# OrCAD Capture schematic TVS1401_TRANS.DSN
size C; title: TVS1401 14-V Bidirectional Flat-Clamp Surge Protection Device; rev: 1.0; note: Datasheet:SLVSEQ2    EVM: NA; note: Synchronous Step Down Converter
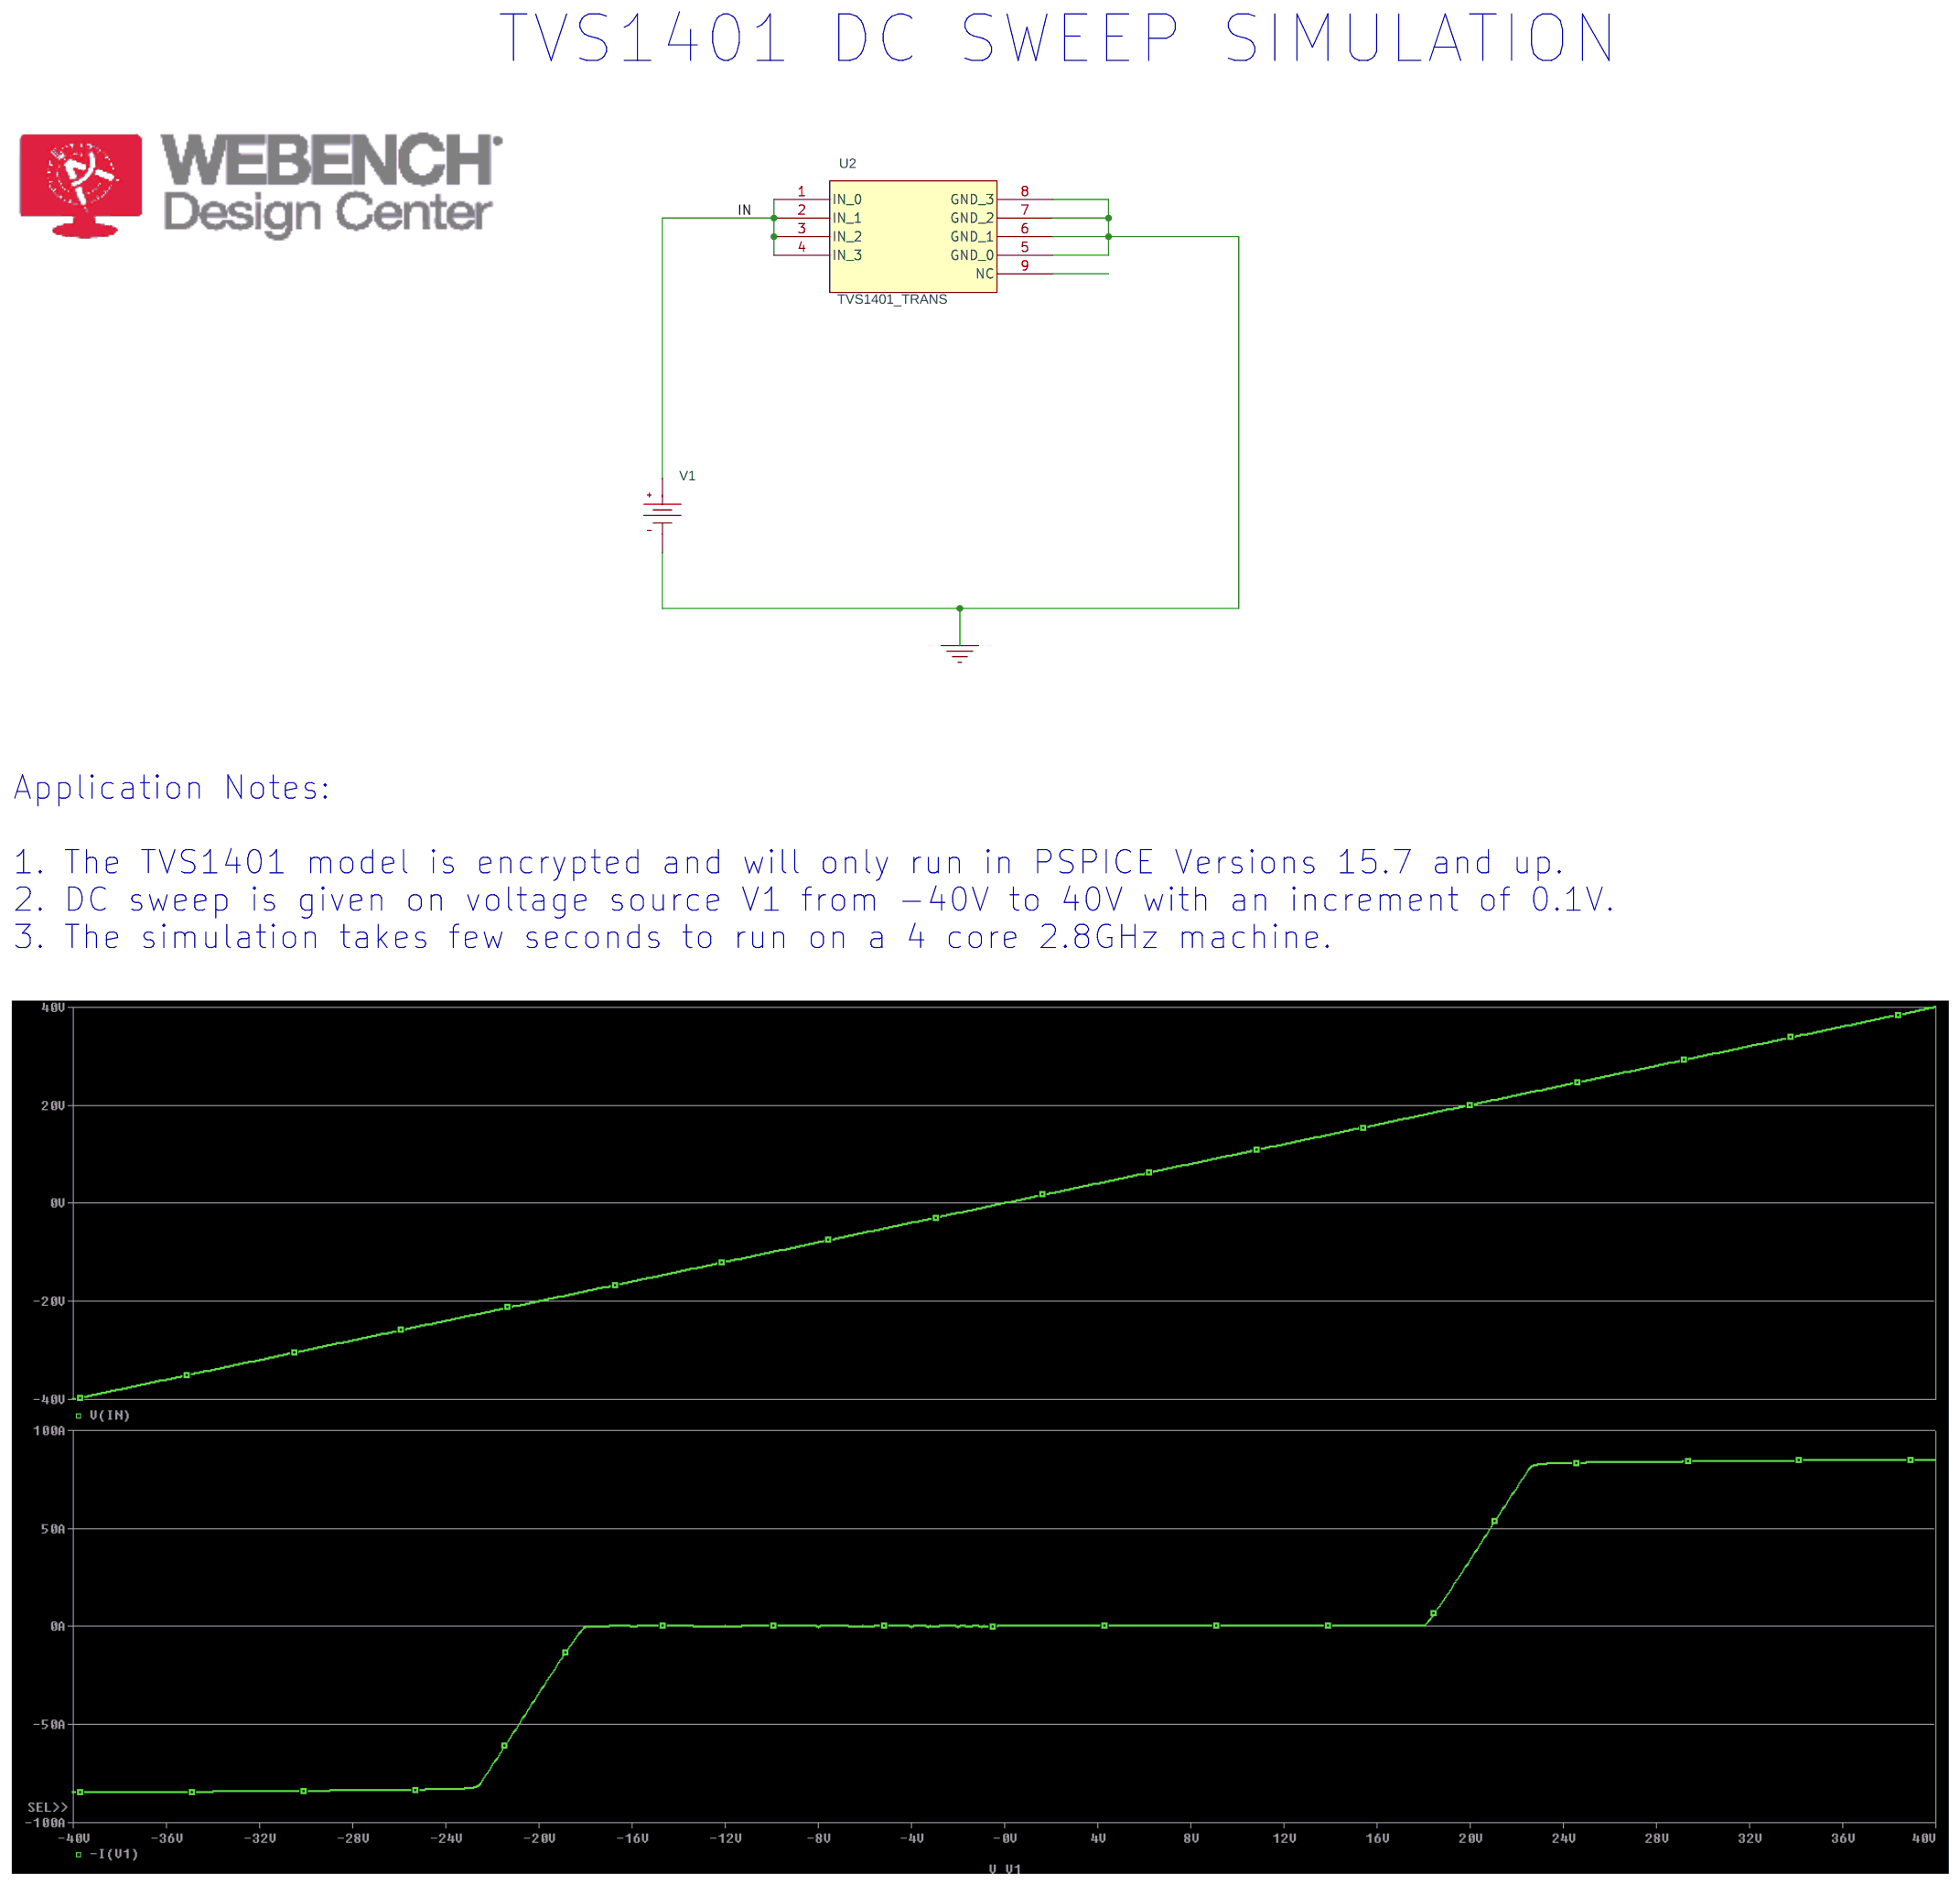
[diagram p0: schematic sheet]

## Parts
U2  TVS1401_TRANS
V1  VDC

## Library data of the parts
U2 = TVS1401_TRANS
V1 = VDC

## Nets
0: U2.5(GND_0) U2.6(GND_1) U2.7(GND_2) U2.8(GND_3) V1.1(-)
IN: U2.1(IN_0) U2.2(IN_1) U2.3(IN_2) U2.4(IN_3) V1.0(+)

Not connected (* = marked no-connect by the designer): U2 9(NC)

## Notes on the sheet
- TVS1401 DC SWEEP SIMULATION
- Application Notes:
  1. The TVS1401 model is encrypted and will only run in PSPICE Versions 15.7 and up.
  2. DC sweep is given on voltage source V1 from -40V to 40V with an increment of 0.1V.
  3. The simulation takes few seconds to run on a 4 core 2.8GHz machine.
